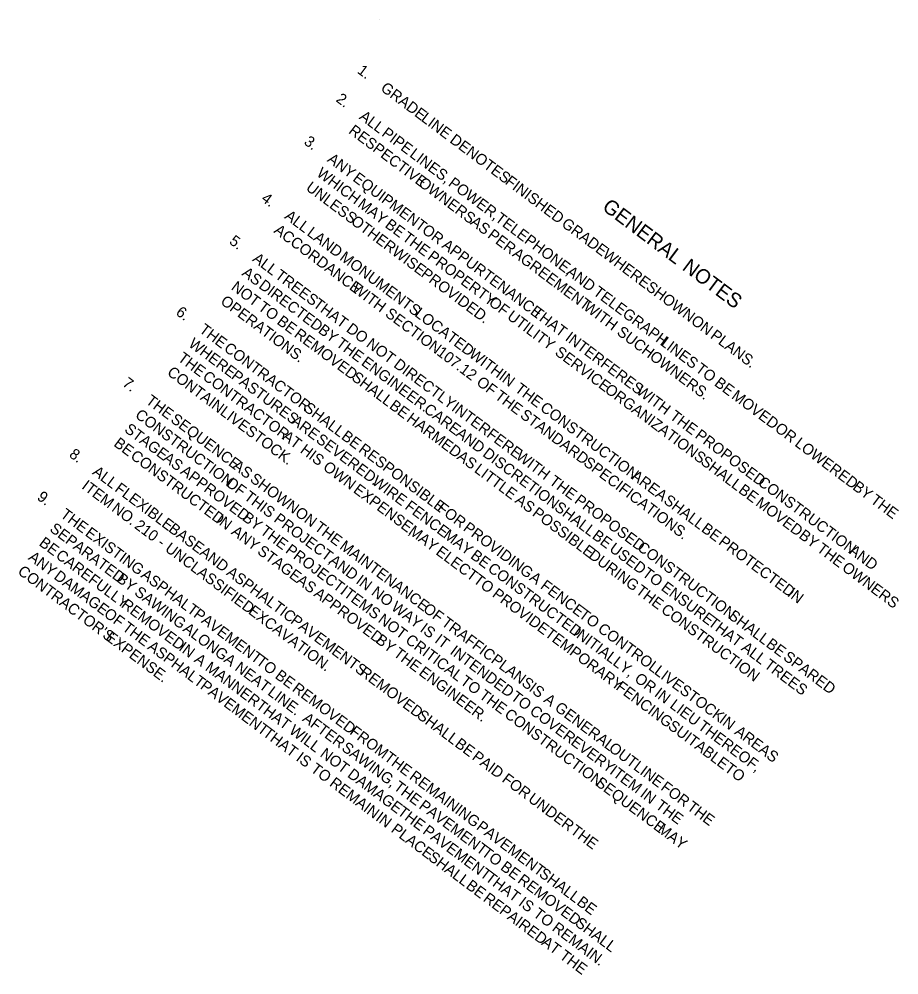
# Model space of a CAD drawing. Extents: x 626494 to 628584, y 365986 to 369269.
# Drawn here: x 627665.6 to 627670.42, y 368674.43 to 368679.68 of the extents above; entities that cross this region are included whole.
import ezdxf

# ---------------------------------------------------------------- set-up
doc = ezdxf.new("R2010")
doc.units = 0
doc.layers.add('Default', color=7, linetype='Continuous')
doc.layers.add('R_Survey Control', color=7, linetype='Continuous')

msp = doc.modelspace()

# ---------------------------------------------------------------- linework, layer by layer
at = {"layer": 'R_Survey Control'}
msp.add_line((627667.5735, 368679.6774), (627667.5735, 368679.6774), dxfattribs=at)

# ---------------------------------------------------------------- texts
at = {"layer": 'Default'}
for s, height, p in [('1.', 0.06, (627667.4468, 368679.3852)), ('GRADE', 0.06, (627667.5746, 368679.2892)), ('2.', 0.06, (627667.3297, 368679.2292)), ('ALL', 0.06, (627667.4575, 368679.1333)), (' LINE', 0.06, (627667.7788, 368679.1359)), ('RESPECTIVE', 0.06, (627667.399, 368679.0553)), (' PIPE', 0.06, (627667.5626, 368679.0544)), ('3.', 0.06, (627667.1541, 368678.9953)), (' DENOTES', 0.06, (627667.9358, 368679.018)), (' LINES,', 0.06, (627667.7154, 368678.9396)), ('ANY', 0.06, (627667.2819, 368678.8994)), ('WHICH', 0.06, (627667.2233, 368678.8214)), (' EQUIPMENT', 0.06, (627667.404, 368678.8077)), (' POWER,', 0.06, (627667.9274, 368678.7805)), (' FINISHED', 0.06, (627668.2395, 368678.7899)), ('UNLESS', 0.06, (627667.1648, 368678.7434)), (' OWNERS', 0.06, (627667.7641, 368678.7811)), ('4.', 0.06, (627666.9199, 368678.6835)), (' MAY', 0.06, (627667.4313, 368678.6652)), ('GENERAL', 0.08, (627668.7892, 368678.6352)), ('ALL', 0.06, (627667.0477, 368678.5875)), (' TELEPHONE,', 0.06, (627668.1846, 368678.5873)), ('ACCORDANCE', 0.06, (627666.9891, 368678.5095)), (' OTHERWISE', 0.06, (627667.3938, 368678.5715)), (' BE', 0.06, (627667.5808, 368678.553)), (' OR', 0.06, (627667.783, 368678.5231)), (' AS', 0.06, (627668.048, 368678.568)), (' GRADE', 0.06, (627668.5488, 368678.5577)), ('5.', 0.06, (627666.7443, 368678.4496)), (' LAND', 0.06, (627667.1527, 368678.5086)), (' THE', 0.06, (627667.6752, 368678.4821)), (' PER', 0.06, (627668.1433, 368678.4964)), (' APPURTENANCE', 0.06, (627667.8923, 368678.441)), ('ALL', 0.06, (627666.8721, 368678.3536)), (' MONUMENTS', 0.06, (627667.3325, 368678.3737)), (' PROPERTY', 0.06, (627667.8137, 368678.3781)), (' AGREEMENT', 0.06, (627668.2793, 368678.3943)), (' WHERE', 0.06, (627668.7736, 368678.3889)), (' NOTES', 0.08, (627669.2042, 368678.3236)), ('AS', 0.06, (627666.8135, 368678.2756)), (' TREES', 0.06, (627666.9771, 368678.2747)), (' PROVIDED.', 0.06, (627667.7779, 368678.2831)), (' AND', 0.06, (627668.5754, 368678.2939)), ('NOT', 0.06, (627666.755, 368678.1977)), (' DIRECTED', 0.06, (627666.8882, 368678.2196)), (' WITH', 0.06, (627667.3985, 368678.2022)), (' SHOWN', 0.06, (627669.0111, 368678.2105)), (' TELEGRAPH', 0.06, (627668.7223, 368678.1835)), ('OPERATIONS.', 0.06, (627666.6964, 368678.1197)), (' TO', 0.06, (627666.8842, 368678.1006)), (' THAT', 0.06, (627667.1863, 368678.1176)), (' OF', 0.06, (627668.1497, 368678.1258)), (' WITH', 0.06, (627668.669, 368678.1017)), ('6.', 0.06, (627666.4516, 368678.0597)), (' SECTION', 0.06, (627667.5814, 368678.0648)), (' LOCATED', 0.06, (627667.7435, 368678.065)), (' UTILITY', 0.06, (627668.2506, 368678.0501)), (' THAT', 0.06, (627668.3872, 368678.0694)), (' BE', 0.06, (627666.9879, 368678.0227)), (' ON', 0.06, (627669.2584, 368678.0248)), ('THE', 0.06, (627666.5793, 368677.9638)), (' REMOVED', 0.06, (627667.0823, 368677.9519)), (' BY', 0.06, (627667.214, 368677.9749)), (' DO', 0.06, (627667.3681, 368677.9811)), (' SUCH', 0.06, (627668.8519, 368677.9643)), (' PLANS.', 0.06, (627669.3649, 368677.9449)), ('WHERE', 0.06, (627666.5208, 368677.8858)), (' THE', 0.06, (627667.3119, 368677.9014)), (' NOT', 0.06, (627667.4781, 368677.8986)), (' INTERFERES', 0.06, (627668.569, 368677.9329)), (' LINES', 0.06, (627669.089, 368677.9082)), (' CONTRACTOR', 0.06, (627666.6973, 368677.8752)), (' 107.12', 0.06, (627667.8644, 368677.8523)), (' WITHIN', 0.06, (627668.0411, 368677.8416)), (' SERVICE', 0.06, (627668.512, 368677.8538)), ('THE', 0.06, (627666.4622, 368677.8078)), (' ENGINEER.', 0.06, (627667.4505, 368677.7973)), (' DIRECTLY', 0.06, (627667.6279, 368677.786)), (' OWNERS.', 0.06, (627669.0319, 368677.8292)), ('CONTAIN', 0.06, (627666.4037, 368677.7299)), (' TO', 0.06, (627669.2832, 368677.7624)), ('7.', 0.06, (627666.1588, 368677.6699)), (' CONTRACTOR', 0.06, (627666.5802, 368677.7193)), (' PASTURES', 0.06, (627666.7377, 368677.723)), (' SHALL', 0.06, (627667.3975, 368677.7152)), (' OF', 0.06, (627668.0821, 368677.6888)), (' BE', 0.06, (627669.3869, 368677.6845)), (' THE', 0.06, (627668.2927, 368677.6526)), (' ORGANIZATIONS', 0.06, (627668.7858, 368677.6482)), (' WITH', 0.06, (627668.9593, 368677.6398)), ('THE', 0.06, (627666.2866, 368677.5739)), (' THE', 0.06, (627668.183, 368677.6131)), (' MOVED', 0.06, (627669.4813, 368677.6137)), (' LIVESTOCK.', 0.06, (627666.676, 368677.5254)), (' SHALL', 0.06, (627667.1342, 368677.5472)), (' BE', 0.06, (627667.6045, 368677.5598)), (' CARE', 0.06, (627667.7937, 368677.5397)), (' INTERFERE', 0.06, (627667.9453, 368677.5477)), (' CONSTRUCTION', 0.06, (627668.4313, 368677.5486)), ('CONSTRUCTION', 0.06, (627666.2281, 368677.496)), (' SEQUENCE', 0.06, (627666.4046, 368677.4854)), (' ARE', 0.06, (627667.0659, 368677.4765)), (' HARMED', 0.06, (627667.6988, 368677.4889)), (' STANDARD', 0.06, (627668.3216, 368677.509)), (' THE', 0.06, (627669.1422, 368677.5025)), ('STAGE', 0.06, (627666.1695, 368677.418)), (' OR', 0.06, (627669.7185, 368677.4355)), (' AT', 0.06, (627667.0171, 368677.3912)), (' SEVERED.', 0.06, (627667.2019, 368677.3744)), (' BE', 0.06, (627667.3411, 368677.3918)), (' AND', 0.06, (627667.9693, 368677.4078)), (' PROPOSED', 0.06, (627669.2808, 368677.3984)), ('BE', 0.06, (627666.111, 368677.34)), (' HIS', 0.06, (627667.1158, 368677.3171)), (' RESPONSIBLE', 0.06, (627667.4355, 368677.3209)), (' LOWERED', 0.06, (627669.8278, 368677.3534)), ('8.', 0.06, (627665.8661, 368677.2801)), (' CONSTRUCTED', 0.06, (627666.1847, 368677.2847)), (' AS', 0.06, (627666.3633, 368677.2725)), (' AS', 0.06, (627667.9751, 368677.2815)), (' DISCRETION', 0.06, (627668.1162, 368677.2975)), (' WITH', 0.06, (627668.2983, 368677.2827)), (' AS', 0.06, (627666.7445, 368677.2301)), (' OWN', 0.06, (627667.2407, 368677.2233)), (' LITTLE', 0.06, (627668.0704, 368677.2099)), (' SPECIFICATIONS.', 0.06, (627668.669, 368677.2481)), (' SHALL', 0.06, (627669.3118, 368677.2532)), ('ALL', 0.06, (627665.9939, 368677.1841)), (' APPROVED', 0.06, (627666.4586, 368677.2009)), (' SHOWN', 0.06, (627666.8398, 368677.1586)), (' AREA', 0.06, (627668.9304, 368677.1738)), ('ITEM', 0.06, (627665.9353, 368677.1061)), (' FLEXIBLE', 0.06, (627666.0989, 368677.1052)), (' OF', 0.06, (627666.7066, 368677.1367)), (' EXPENSE,', 0.06, (627667.4067, 368677.0987)), (' WIRE', 0.06, (627667.5092, 368677.1437)), (' THE', 0.06, (627668.4812, 368677.1453)), (' BE', 0.06, (627669.5188, 368677.0978)), (' CONSTRUCTION', 0.06, (627669.625, 368677.14)), (' BY', 0.06, (627670.1451, 368677.1152)), ('9.', 0.06, (627665.6905, 368677.0462)), (' THIS', 0.06, (627666.8074, 368677.0609)), (' NO.', 0.06, (627666.0815, 368676.9964)), (' FENCE', 0.06, (627667.6897, 368677.0081)), (' FOR', 0.06, (627667.8659, 368676.9977)), (' AS', 0.06, (627668.2932, 368677.0426)), (' SHALL', 0.06, (627668.5096, 368677.0021)), (' PROPOSED', 0.06, (627668.6198, 368677.0412)), (' SHALL', 0.06, (627669.1084, 368677.0401)), (' MOVED', 0.06, (627669.6132, 368677.0269)), (' THE', 0.06, (627670.243, 368677.0417)), ('THE', 0.06, (627665.8183, 368676.9502)), (' BY', 0.06, (627666.7983, 368676.9459)), (' ON', 0.06, (627667.0871, 368676.9729)), (' POSSIBLE', 0.06, (627668.3885, 368676.9711)), (' 210', 0.06, (627666.2067, 368676.9024)), (' IN', 0.06, (627666.6531, 368676.933)), (' PROJECT,', 0.06, (627666.9709, 368676.9382)), (' THE', 0.06, (627667.1936, 368676.8929)), (' PROVIDING', 0.06, (627668.0096, 368676.8898)), ('SEPARATED', 0.06, (627665.7597, 368676.8722)), (' EXISTING', 0.06, (627665.9362, 368676.8616)), (' BASE', 0.06, (627666.3933, 368676.8842)), (' ANY', 0.06, (627666.7375, 368676.8696)), (' THE', 0.06, (627666.8963, 368676.8723)), (' MAY', 0.06, (627667.7099, 368676.871)), (' MAY', 0.06, (627667.9003, 368676.85)), (' BE', 0.06, (627668.7165, 368676.8467)), (' BE', 0.06, (627669.3154, 368676.8847)), (' BY', 0.06, (627669.8504, 368676.8488)), ('BE', 0.06, (627665.7012, 368676.7943)), (' -', 0.06, (627666.3326, 368676.8078)), (' MAINTENANCE', 0.06, (627667.3321, 368676.7889)), (' PROTECTED', 0.06, (627669.4098, 368676.8139)), (' CAREFULLY', 0.06, (627665.7749, 368676.7389)), (' UNCLASSIFIED', 0.06, (627666.3743, 368676.7765)), (' AND', 0.06, (627666.564, 368676.756)), (' STAGE', 0.06, (627666.8802, 368676.7625)), (' PROJECT.', 0.06, (627667.0348, 368676.7683)), (' ELECT', 0.06, (627667.8594, 368676.7587)), (' BE', 0.06, (627668.0498, 368676.7377)), (' DURING', 0.06, (627668.6969, 368676.7395)), (' USED', 0.06, (627668.8109, 368676.7758)), (' CONSTRUCTION', 0.06, (627668.964, 368676.7828)), (' THE', 0.06, (627669.9484, 368676.7752)), (' AND', 0.06, (627670.1241, 368676.7652)), ('ANY', 0.06, (627665.6426, 368676.7163)), (' AND', 0.06, (627667.2742, 368676.7104)), ("CONTRACTOR'S", 0.06, (627665.5841, 368676.6383)), (' ASPHALTIC', 0.06, (627666.7109, 368676.6457)), (' CONSTRUCTED', 0.06, (627668.1441, 368676.6669)), (' TO', 0.06, (627668.9912, 368676.6404)), (' OWNERS', 0.06, (627670.0869, 368676.6712)), (' DAMAGE', 0.06, (627665.7647, 368676.6246)), (' BY', 0.06, (627666.1082, 368676.6106)), (' ASPHALT', 0.06, (627666.2416, 368676.6323)), (' AS', 0.06, (627667.0946, 368676.6015)), (' IN', 0.06, (627667.4212, 368676.6001)), (' TO', 0.06, (627668.065, 368676.6043)), (' A', 0.06, (627668.3725, 368676.6173)), (' SAWING', 0.06, (627666.2061, 368676.537)), (' ITEMS', 0.06, (627667.3359, 368676.5422)), (' NO', 0.06, (627667.5056, 368676.5367)), (' PROVIDE', 0.06, (627668.1687, 368676.5265)), (' FENCE', 0.06, (627668.433, 368676.5719)), (' THE', 0.06, (627668.956, 368676.545)), (' ENSURE', 0.06, (627669.0949, 368676.5626)), (' IN', 0.06, (627669.7878, 368676.53)), (' REMOVED', 0.06, (627666.1345, 368676.4689)), (' APPROVED', 0.06, (627667.1899, 368676.5299)), (' EXCAVATION.', 0.06, (627666.8311, 368676.4335)), (' WAY', 0.06, (627667.6148, 368676.4547)), (' OF', 0.06, (627667.7896, 368676.4454)), (' TO', 0.06, (627668.6436, 368676.4137)), (' CONSTRUCTION', 0.06, (627669.0946, 368676.4409)), (' OF', 0.06, (627666.039, 368676.4187)), (' PAVEMENT', 0.06, (627666.5304, 368676.4155)), (' PAVEMENTS', 0.06, (627667.0629, 368676.3814)), (' NOT', 0.06, (627667.5427, 368676.3869)), (' TRAFFIC', 0.06, (627667.8904, 368676.3697)), (' THAT', 0.06, (627669.3524, 368676.3692)), (' SHALL', 0.06, (627669.4631, 368676.408)), (' THE', 0.06, (627666.1399, 368676.3429)), (' ALONG', 0.06, (627666.4721, 368676.3373)), (' IS', 0.06, (627667.7729, 368676.336)), (' TEMPORARY', 0.06, (627668.457, 368676.31)), (' INITIALLY,', 0.06, (627668.6124, 368676.3152)), (' CONTROL', 0.06, (627668.7473, 368676.3359)), (' EXPENSE.', 0.06, (627666.0483, 368676.2897)), (' BY', 0.06, (627667.5296, 368676.2748)), (' CRITICAL', 0.06, (627667.6925, 368676.2744)), (' IT', 0.06, (627667.8533, 368676.2756)), (' ASPHALT', 0.06, (627666.2785, 368676.2389)), (' IN', 0.06, (627666.4497, 368676.2322)), (' INTENDED', 0.06, (627667.937, 368676.2127)), (' ALL', 0.06, (627669.5342, 368676.2327)), (' BE', 0.06, (627669.6701, 368676.2526)), (' A', 0.06, (627666.5341, 368676.1689)), (' A', 0.06, (627666.6968, 368676.1686)), (' TO', 0.06, (627666.8738, 368676.1576)), (' THE', 0.06, (627667.6275, 368676.2013)), (' PLANS', 0.06, (627668.1621, 368676.1657)), (' SPARED', 0.06, (627669.7644, 368676.1818)), (' MANNER', 0.06, (627666.5946, 368676.1234)), (' NEAT', 0.06, (627666.7573, 368676.1232)), (' LIVESTOCK', 0.06, (627669.0571, 368676.1032)), (' TREES', 0.06, (627669.6599, 368676.1383)), (' BE', 0.06, (627666.9775, 368676.0797)), (' REMOVED', 0.06, (627667.4414, 368676.0972)), (' ENGINEER.', 0.06, (627667.7661, 368676.0973)), (' TO', 0.06, (627667.9933, 368676.0485)), (' OR', 0.06, (627668.9488, 368676.0626)), (' PAVEMENT', 0.06, (627666.5673, 368676.022)), (' REMOVED', 0.06, (627667.0719, 368676.0089)), (' IS', 0.06, (627668.3706, 368676.0091)), (' FENCING', 0.06, (627668.847, 368676.0172)), (' LINE.', 0.06, (627666.9371, 368675.9882)), (' THE', 0.06, (627668.097, 368675.9707)), (' TO', 0.06, (627668.2703, 368675.9625)), (' IN', 0.06, (627669.0581, 368675.9806)), (' THAT', 0.06, (627666.8727, 368675.9146)), (' A', 0.06, (627668.4509, 368675.9488)), (' GENERAL', 0.06, (627668.5114, 368675.9033)), (' LIEU', 0.06, (627669.1425, 368675.9172)), (' SHALL', 0.06, (627667.7566, 368675.8605)), (' CONSTRUCTION', 0.06, (627668.2356, 368675.8666)), (' COVER', 0.06, (627668.374, 368675.8846)), ('  AFTER', 0.06, (627667.11, 368675.8583)), (' SUITABLE', 0.06, (627669.1323, 368675.803)), (' THEREOF,', 0.06, (627669.2966, 368675.8015)), (' IN', 0.06, (627669.413, 368675.836)), (' THAT', 0.06, (627666.9107, 368675.7641)), (' WILL', 0.06, (627667.0546, 368675.778)), (' FROM', 0.06, (627667.3871, 368675.7722)), (' AREAS', 0.06, (627669.4974, 368675.7726)), (' BE', 0.06, (627667.9636, 368675.7051)), (' EVERY', 0.06, (627668.5994, 368675.7154)), (' NOT', 0.06, (627667.2247, 368675.6503)), (' SAWING,', 0.06, (627667.3427, 368675.6836)), (' THE', 0.06, (627667.5758, 368675.6305)), (' PAID', 0.06, (627668.0579, 368675.6342)), (' OUTLINE', 0.06, (627668.8074, 368675.6811)), (' IS', 0.06, (627667.0925, 368675.6276)), (' TO', 0.06, (627667.1728, 368675.5673)), (' DAMAGE', 0.06, (627667.3746, 368675.5377)), (' REMAINING', 0.06, (627667.7143, 368675.5265)), (' ITEM', 0.06, (627668.8128, 368675.5551)), (' TO', 0.06, (627669.4422, 368675.5702)), (' REMAIN', 0.06, (627667.2765, 368675.4894)), (' THE', 0.06, (627667.628, 368675.4694)), (' FOR', 0.06, (627668.2218, 368675.5112)), (' SEQUENCE', 0.06, (627668.7347, 368675.4918)), (' IN', 0.06, (627668.9795, 368675.4299)), (' FOR', 0.06, (627669.0928, 368675.4668)), (' UNDER', 0.06, (627668.3655, 368675.4033)), (' THE', 0.06, (627669.064, 368675.3665)), (' THE', 0.06, (627667.6489, 368675.3317)), (' PAVEMENT', 0.06, (627667.7665, 368675.3653)), (' THE', 0.06, (627669.2365, 368675.3589)), (' IN', 0.06, (627667.5293, 368675.2996)), (' PLACE', 0.06, (627667.6138, 368675.2362)), (' PAVEMENT', 0.06, (627667.7875, 368675.2277)), (' PAVEMENT', 0.06, (627668.0816, 368675.2507)), (' THE', 0.06, (627668.5972, 368675.2293)), (' MAY', 0.06, (627669.0746, 368675.2366)), (' TO', 0.06, (627668.11, 368675.1075)), (' SHALL', 0.06, (627667.8176, 368675.0831)), (' BE', 0.06, (627668.2137, 368675.0296)), (' THAT', 0.06, (627668.1309, 368674.9698)), (' REMOVED', 0.06, (627668.308, 368674.9587)), (' SHALL', 0.06, (627668.425, 368674.9928)), (' BE', 0.06, (627668.0246, 368674.9277)), (' REPAIRED', 0.06, (627668.119, 368674.8568)), (' IS', 0.06, (627668.3128, 368674.8333)), (' BE', 0.06, (627668.632, 368674.8374)), (' TO', 0.06, (627668.3931, 368674.773)), (' REMAIN.', 0.06, (627668.4968, 368674.6951)), (' SHALL', 0.06, (627668.6232, 368674.7221)), (' AT', 0.06, (627668.4388, 368674.6167)), (' THE', 0.06, (627668.5375, 368674.5426))]:
    msp.add_text(s, height=height, rotation=323.0976, dxfattribs=at).set_placement(p)

doc.saveas('drawing.dxf')
